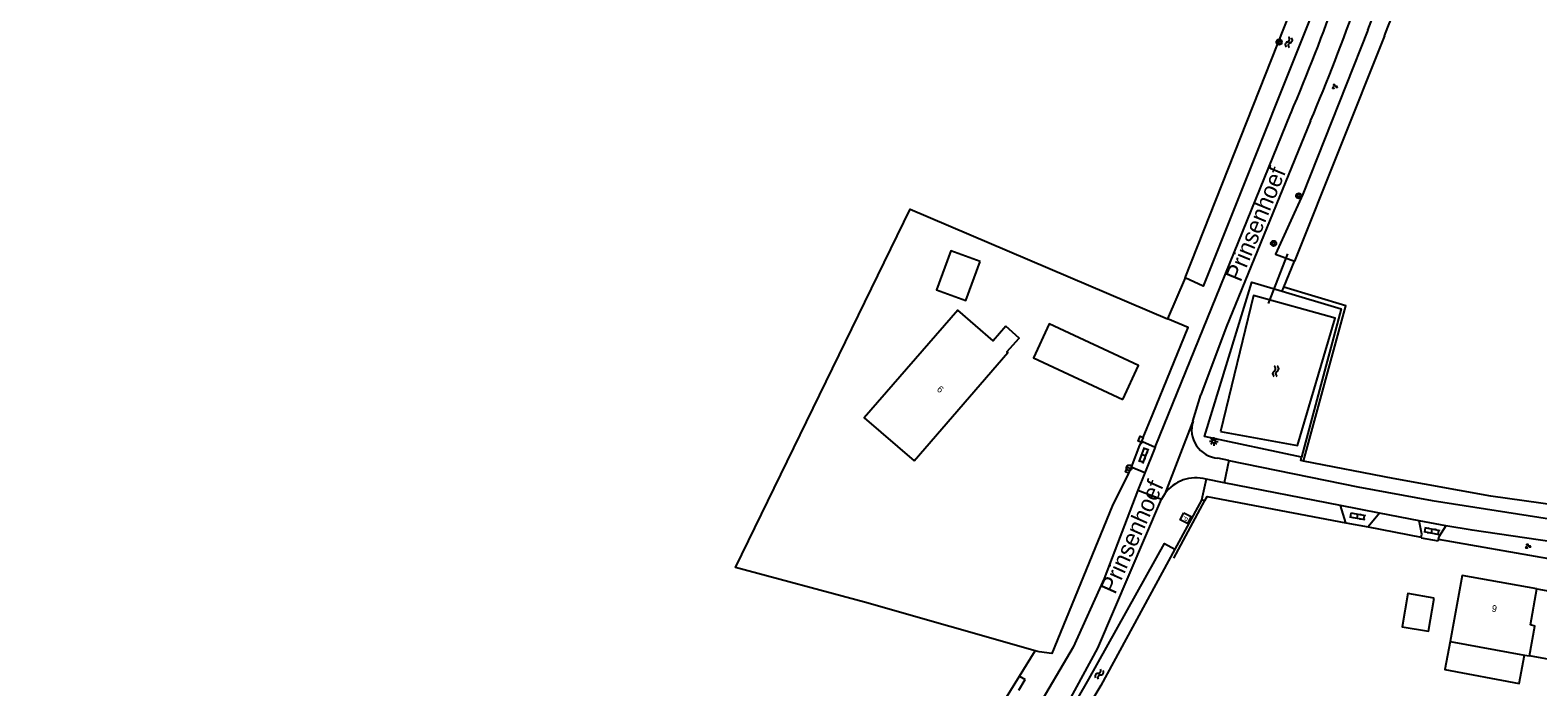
# Model space of a CAD drawing. Extents: x 124000 to 129000, y 395500 to 397503.
# Drawn here: x 125592.7 to 125816.2, y 397221.4 to 397318.7 of the extents above; entities that cross this region are included whole.
import ezdxf

# ---------------------------------------------------------------- set-up
doc = ezdxf.new("R2010")
doc.units = 0
for name, color, linetype in [('gg-afsc-draadraster', 7, 'Continuous'), ('gg-afsc-erfafscheiding', 7, 'Continuous'), ('gg-afsc-hekwerk', 7, 'Continuous'), ('gg-afsc-muur', 7, 'Continuous'), ('gg-anno-huisnummerreeks BGT', 7, 'Continuous'), ('gg-anno-openbare ruimte label', 7, 'Continuous'), ('gg-bbg-bijgebouw', 7, 'Continuous'), ('gg-bbg-gedigitaliseerde bebouwing', 7, 'Continuous'), ('gg-bbg-gedigitaliseerde bijgebouw', 7, 'Continuous'), ('gg-bbg-hoofdgebouw', 7, 'Continuous'), ('gg-bbg-luifel en loopbrug', 7, 'Continuous'), ('gg-bbg-tussenscheiding', 7, 'Continuous'), ('gg-knt-bronhoudergrens', 7, 'Continuous'), ('gg-knt-onverhard', 7, 'Continuous'), ('gg-knt-verharding', 7, 'Continuous'), ('gg-knt-verharding nz', 7, 'Continuous'), ('gg-kntw-bovenkant insteek waterloop', 7, 'Continuous'), ('gg-kwrk-duiker nz buis', 7, 'Continuous'), ('gt-grn-groengrens', 7, 'Continuous'), ('gt-grn-vlakafsluiter', 7, 'Continuous'), ('gt-grn-weggrens', 7, 'Continuous'), ('gt-symb-boom', 7, 'Continuous'), ('gt-symb-brandput', 7, 'Continuous'), ('gt-symb-groenvak', 7, 'Continuous'), ('gt-symb-hoogtemerk', 7, 'Continuous'), ('gt-symb-klinker verharding', 7, 'Continuous'), ('gt-symb-lichtmast', 7, 'Continuous'), ('gt-symb-watersymbool', 7, 'Continuous')]:
    doc.layers.add(name, color=color, linetype=linetype)

# ---------------------------------------------------------------- blocks, each defined once
blk = doc.blocks.new('gt0-BOOM')
at = {"layer": 'gt-symb-boom'}
for radius in [0.4, 0.2]:
    blk.add_circle((0, 0), radius, dxfattribs=at)
blk = doc.blocks.new('gt0-WA')
at = {"layer": 'gt-symb-watersymbool'}
for centre, start, end in [((-0.32, 0.02), 28.0725, 151.9275), ((0.43, 0.42), 208.0725, 331.9275), ((-0.32, -0.43), 28.0725, 151.9275), ((0.43, -0.03), 208.0725, 331.9275)]:
    blk.add_arc(centre, 0.425, start, end, dxfattribs=at)
blk = doc.blocks.new('gt0-KL1')
at = {"layer": 'gt-symb-klinker verharding'}
for p, q in [((-1.15, 0.3), (1.15, 0.3)), ((-1, -0.3), (-1, 0.3)), ((-0.5, 0.3), (-0.5, 0.45)), ((0, -0.3), (0, 0.3)), ((0.5, 0.3), (0.5, 0.45)), ((1, -0.3), (1, 0.3)), ((-1.15, -0.3), (1.15, -0.3)), ((-0.5, -0.45), (-0.5, -0.3)), ((0.5, -0.45), (0.5, -0.3))]:
    blk.add_line(p, q, dxfattribs=at)
blk = doc.blocks.new('gt0-LMAST')
at = {"layer": 'gt-symb-lichtmast'}
for p, q in [((-0.18, 0.17), (-0.45, 0.44)), ((-0.01, 0.25), (-0.01, 0.62)), ((0.17, 0.17), (0.44, 0.44)), ((-0.26, 0), (-0.63, 0)), ((-0.18, -0.18), (-0.45, -0.45)), ((-0.01, -0.25), (-0.01, -0.63)), ((0.44, -0.45), (0.17, -0.18)), ((0.24, 0), (0.62, 0))]:
    blk.add_line(p, q, dxfattribs=at)
blk.add_circle((-0.01, 0), 0.25, dxfattribs=at)
blk = doc.blocks.new('gt0-GRVAK')
at = {"layer": 'gt-symb-groenvak'}
for p, q in [((-0.11, 0.19), (-0.23, 0.24)), ((-0.18, 0.15), (0.09, 0.15)), ((-0.09, 0.21), (-0.16, 0.32)), ((-0.05, 0.21), (-0.05, 0.39)), ((0, 0.21), (0.06, 0.32)), ((0.01, 0.19), (0.13, 0.24)), ((0.26, -0.05), (0.2, 0.06)), ((0.3, -0.05), (0.3, 0.13)), ((0.35, -0.05), (0.41, 0.06)), ((-0.25, -0.23), (-0.36, -0.18)), ((-0.32, -0.26), (-0.05, -0.26)), ((-0.23, -0.21), (-0.29, -0.09)), ((-0.18, -0.2), (-0.18, -0.02)), ((-0.14, -0.21), (-0.07, -0.09)), ((-0.12, -0.23), (0, -0.18)), ((0.24, -0.07), (0.12, -0.02)), ((0.17, -0.11), (0.44, -0.11)), ((0.37, -0.07), (0.49, -0.02))]:
    blk.add_line(p, q, dxfattribs=at)
blk = doc.blocks.new('gt0-BPUT')
at = {"layer": 'gt-symb-brandput'}
blk.add_lwpolyline([(-0.6, -0.6), (-0.6, 0.6), (0.6, 0.6), (0.6, -0.6)], close=True, dxfattribs=at)
blk.add_text('P', height=0.7, dxfattribs=at).set_placement((-0.23, -0.35))
blk = doc.blocks.new('gt0-HMERK')
at = {"layer": 'gt-symb-hoogtemerk'}
blk.add_circle((0, 0), 0.4, dxfattribs=at)
blk.add_text('N.A.P', height=0.2, dxfattribs=at).set_placement((-0.35, -0.1))

msp = doc.modelspace()

# ---------------------------------------------------------------- linework, layer by layer
at = {"layer": 'gg-afsc-draadraster'}
for p, q in [((125742.29, 397226.56), (125741.72, 397226.72)), ((125739.37, 397222.94), (125740.23, 397222.45))]:
    msp.add_line(p, q, dxfattribs=at)
for points in [[(125741.72, 397226.72), (125716.39, 397233.93), (125697.28, 397239.08), (125723.17, 397292.15), (125761.34, 397275.92)], [(125781.5, 397254.82), (125787.78, 397277.85), (125778.58, 397280.61)], [(125642.65, 397110.93), (125650.08, 397115.76), (125657.43, 397120.69), (125663.34, 397125.22), (125669.13, 397130.47), (125677.55, 397139.59), (125698.48, 397164.07), (125708.62, 397176.8), (125716.67, 397187.69), (125724.43, 397198.85), (125739.37, 397222.94)]]:
    msp.add_lwpolyline(points, dxfattribs=at)
at = {"layer": 'gg-afsc-erfafscheiding'}
for p, q in [((125762.26, 397240.47), (125766.86, 397248.97)), ((125791.07, 397245.07), (125798.95, 397243.56)), ((125801.47, 397243.24), (125817.83, 397240.38))]:
    msp.add_line(p, q, dxfattribs=at)
msp.add_lwpolyline([(125766.86, 397248.97), (125767.19, 397249.57), (125787.74, 397245.69)], dxfattribs=at)
at = {"layer": 'gg-afsc-hekwerk'}
for points in [[(125781.21, 397255.43), (125766.81, 397258.46), (125773.81, 397281.37), (125778.34, 397280)], [(125778.34, 397280), (125787.07, 397277.38), (125781.21, 397255.43)], [(125781.5, 397254.82), (125781.1, 397254.9), (125781.21, 397255.43)], [(125860.69, 397244.76), (125860, 397244.82), (125859.93, 397243.49), (125842.01, 397245.47), (125824.09, 397247.55), (125809.27, 397249.63), (125794.76, 397252.24), (125781.5, 397254.82)]]:
    msp.add_lwpolyline(points, dxfattribs=at)
at = {"layer": 'gg-afsc-muur'}
for p, q in [((125757.73, 397258.34), (125757.44, 397257.63)), ((125755.86, 397253.76), (125755.56, 397253.03))]:
    msp.add_line(p, q, dxfattribs=at)
for points in [[(125757.44, 397257.63), (125756.99, 397257.81), (125757.29, 397258.53), (125757.73, 397258.34)], [(125755.56, 397253.03), (125755.1, 397253.23), (125755.4, 397253.95), (125755.86, 397253.76)]]:
    msp.add_lwpolyline(points, dxfattribs=at)
at = {"layer": 'gg-bbg-bijgebouw'}
for points in [[(125754.69, 397263.97), (125757.04, 397269.02), (125743.8, 397275.17), (125741.45, 397270.12), (125754.69, 397263.97)], [(125800.88, 397234.51), (125796.95, 397235.2), (125796.09, 397230.29), (125800.02, 397229.61), (125800.88, 397234.51)]]:
    msp.add_lwpolyline(points, dxfattribs=at)
at = {"layer": 'gg-bbg-gedigitaliseerde bebouwing'}
msp.add_lwpolyline([(125737.37, 397274.84), (125735.46, 397272.65), (125730.23, 397277.21), (125716.37, 397261.27), (125723.77, 397254.85)], dxfattribs=at)
at = {"layer": 'gg-bbg-gedigitaliseerde bijgebouw'}
msp.add_lwpolyline([(125733.55, 397284.42), (125729.22, 397286.01), (125727.09, 397280.23), (125731.43, 397278.64), (125733.55, 397284.42)], dxfattribs=at)
at = {"layer": 'gg-bbg-hoofdgebouw'}
for p, q in [((125803.23, 397228.08), (125814.25, 397226.09)), ((125814.25, 397226.09), (125815.01, 397225.95))]:
    msp.add_line(p, q, dxfattribs=at)
for points in [[(125723.77, 397254.85), (125737.67, 397270.95), (125737.51, 397271.02), (125739.35, 397273.05), (125737.37, 397274.84)], [(125816.06, 397235.9), (125805, 397237.9), (125803.23, 397228.08)], [(125816.06, 397235.9), (125827.85, 397233.78), (125826.08, 397223.96), (125815.01, 397225.95)]]:
    msp.add_lwpolyline(points, dxfattribs=at)
at = {"layer": 'gg-bbg-luifel en loopbrug'}
msp.add_lwpolyline([(125803.23, 397228.08), (125802.45, 397223.95), (125813.45, 397221.88), (125814.25, 397226.09)], dxfattribs=at)
at = {"layer": 'gg-bbg-tussenscheiding'}
msp.add_lwpolyline([(125815.01, 397225.95), (125815.76, 397230.38), (125815.13, 397230.59), (125816.06, 397235.9)], dxfattribs=at)
at = {"layer": 'gg-knt-bronhoudergrens'}
msp.add_line((125739.37, 397222.94), (125741.72, 397226.72), dxfattribs=at)
at = {"layer": 'gg-knt-onverhard'}
for points in [[(125756.93, 397250.55), (125751.92, 397237.41), (125747.34, 397227.24), (125741.75, 397217.78), (125735.38, 397208.19), (125729.64, 397199.42), (125720.97, 397187.07), (125714.45, 397178.02), (125707.31, 397168.67), (125700.08, 397159.6), (125693.27, 397151.32), (125685.78, 397142.8), (125678.08, 397134.37), (125669.79, 397126.12), (125660.96, 397118.64), (125651.56, 397112.01), (125641.81, 397105.88), (125631.9, 397099.39), (125622.1, 397093.12), (125612.4, 397086.72), (125602.25, 397080.32), (125592.69, 397074.68)], [(125594.39, 397071.5), (125605.9, 397078.13), (125617.48, 397085.31), (125629.25, 397092.48), (125640.98, 397100.11), (125652.95, 397108.25), (125661.79, 397114.35), (125670.36, 397121.2), (125679.79, 397130.22), (125688.65, 397139.93), (125697.18, 397149.89), (125705.54, 397160.37), (125714.15, 397171.43), (125722.32, 397182.61), (125729.65, 397193.12), (125737.34, 397204.28), (125744.49, 397215.1), (125750.97, 397227.13), (125760.44, 397249.2)]]:
    msp.add_lwpolyline(points, dxfattribs=at)
at = {"layer": 'gg-knt-verharding'}
for p, q in [((125759.5, 397256.88), (125779.6, 397306.38)), ((125765.1, 397260.77), (125766.24, 397264.67)), ((125759.5, 397256.88), (125757.96, 397253.08)), ((125770.4, 397254.94), (125768.8, 397255.27)), ((125757.96, 397253.08), (125755.93, 397253.94)), ((125757.96, 397253.08), (125756.93, 397250.55)), ((125756.93, 397250.55), (125760.44, 397249.2)), ((125769.74, 397251.61), (125767.03, 397252.14)), ((125786.98, 397248.24), (125769.74, 397251.61)), ((125760.92, 397250), (125760.44, 397249.2)), ((125792.75, 397247.11), (125786.98, 397248.24)), ((125787.74, 397245.69), (125786.98, 397248.24)), ((125792.75, 397247.11), (125791.07, 397245.07)), ((125798.64, 397245.96), (125792.75, 397247.11)), ((125802.6, 397245.24), (125798.64, 397245.96)), ((125798.93, 397243.44), (125798.95, 397243.56)), ((125801.47, 397243.24), (125801.43, 397243.01))]:
    msp.add_line(p, q, dxfattribs=at)
for points in [[(125782.53, 397305.26), (125770.03, 397274.69), (125766.24, 397264.67)], [(125757.17, 397257.2), (125757.62, 397257.73), (125759.5, 397256.88)], [(125770.4, 397254.94), (125789.54, 397251), (125800.58, 397249.01), (125821.12, 397245.8), (125842.23, 397243.55), (125858.93, 397242.05), (125886.98, 397239.73), (125895.9, 397239.33)], [(125798.95, 397243.56), (125799.03, 397244.01), (125798.64, 397245.96)], [(125802.6, 397245.24), (125801.54, 397243.6), (125801.47, 397243.24)], [(125818.28, 397242.85), (125806.48, 397244.61), (125802.6, 397245.24)]]:
    msp.add_lwpolyline(points, dxfattribs=at)
for centre, radius, start, end in [((125495.48, 397427.25), 308.77, 336.9529, 344.0467), ((125497.35, 397426.68), 309.95, 336.9367, 344.0641), ((125769.12, 397259.47), 4.22, 162.1014, 265.6434), ((125765.49, 397246.73), 5.62, 74.0858, 144.4358)]:
    msp.add_arc(centre, radius, start, end, dxfattribs=at)
at = {"layer": 'gg-knt-verharding nz'}
msp.add_line((125770.4, 397254.94), (125769.74, 397251.61), dxfattribs=at)
at = {"layer": 'gg-kntw-bovenkant insteek waterloop'}
msp.add_line((125793.48, 397317.87), (125780.13, 397284.47), dxfattribs=at)
for points in [[(125787.48, 397342.4), (125789.8, 397341.66), (125786.9, 397331.61), (125766.62, 397280.77), (125763.93, 397282)], [(125763.93, 397282), (125784.1, 397332.97), (125786.34, 397340.47)], [(125791.02, 397318.7), (125781.38, 397294.39), (125777.34, 397285.49), (125780.13, 397284.47)], [(125769.18, 397259.22), (125780.62, 397257.14), (125786.2, 397276), (125774.08, 397279.38), (125769.18, 397259.22)], [(125737.33, 397198.19), (125736.58, 397198.69), (125736.62, 397199.8), (125749.64, 397222.5), (125760.87, 397242.64), (125762.4, 397241.8)], [(125762.4, 397241.8), (125751.42, 397221.6), (125738.26, 397199.47)]]:
    msp.add_lwpolyline(points, dxfattribs=at)
for centre, radius, start, end in [((125598.49, 397393.73), 206.63, 338.7096, 350.9678), ((125633.52, 397382.7), 172.6, 337.9377, 352.7779)]:
    msp.add_arc(centre, radius, start, end, dxfattribs=at)
at = {"layer": 'gg-kwrk-duiker nz buis'}
msp.add_line((125776.28, 397278.18), (125779.14, 397285.55), dxfattribs=at)
at = {"layer": 'gt-grn-groengrens'}
for p, q in [((125778.58, 397280.61), (125780.13, 397284.47)), ((125763.93, 397282), (125761.34, 397275.92)), ((125778.34, 397280), (125778.58, 397280.61)), ((125757.44, 397257.63), (125757.17, 397257.2)), ((125755.56, 397253.03), (125753.12, 397248.17)), ((125755.93, 397253.94), (125755.86, 397253.76)), ((125767.03, 397252.14), (125766.37, 397249.06)), ((125766.37, 397249.06), (125762.4, 397241.8)), ((125766.86, 397248.97), (125766.37, 397249.06))]:
    msp.add_line(p, q, dxfattribs=at)
for points in [[(125757.73, 397258.34), (125759.17, 397261.77), (125764.4, 397274.61), (125761.34, 397275.92)], [(125753.12, 397248.17), (125744.18, 397226.33), (125742.29, 397226.56)]]:
    msp.add_lwpolyline(points, dxfattribs=at)
at = {"layer": 'gt-grn-vlakafsluiter'}
msp.add_line((125739.27, 397220.88), (125740.23, 397222.45), dxfattribs=at)
at = {"layer": 'gt-grn-weggrens'}
for p, q in [((125765.1, 397260.77), (125760.92, 397250)), ((125757.17, 397257.2), (125755.93, 397253.94)), ((125787.74, 397245.69), (125791.07, 397245.07)), ((125798.93, 397243.44), (125801.43, 397243.01))]:
    msp.add_line(p, q, dxfattribs=at)

# ---------------------------------------------------------------- block references
at = {"layer": 'gt-symb-boom'}
for p in [(125777.87, 397316.93), (125780.78, 397294.15), (125777.05, 397287.1)]:
    msp.add_blockref('gt0-BOOM', p, dxfattribs=at)
at = {"layer": 'gt-symb-brandput', "rotation": -116.7455097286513}
msp.add_blockref('gt0-BPUT', (125764.01, 397246.38), dxfattribs=at)
at = {"layer": 'gt-symb-groenvak'}
for p in [(125786.09, 397310.35), (125814.74, 397242.23)]:
    msp.add_blockref('gt0-GRVAK', p, dxfattribs=at)
at = {"layer": 'gt-symb-hoogtemerk'}
msp.add_blockref('gt0-HMERK', (125755.63, 397253.85), dxfattribs=at)
at = {"layer": 'gt-symb-klinker verharding'}
for p, rotation in [((125757.8, 397255.68), 68.9542591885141), ((125789.51, 397246.66), -9.905079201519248), ((125800.52, 397244.47), -10.309970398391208)]:
    msp.add_blockref('gt0-KL1', p, dxfattribs=dict(at, rotation=rotation))
at = {"layer": 'gt-symb-lichtmast'}
msp.add_blockref('gt0-LMAST', (125768.19, 397257.75), dxfattribs=at)
at = {"layer": 'gt-symb-watersymbool'}
for p, rotation in [((125779.33, 397316.95), -103.06333733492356), ((125777.36, 397268.21), -90.00000000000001), ((125751.18, 397223.21), 59.871399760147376)]:
    msp.add_blockref('gt0-WA', p, dxfattribs=dict(at, rotation=rotation))

# ---------------------------------------------------------------- texts
at = {"layer": 'gg-anno-huisnummerreeks BGT'}
for s, rotation, p in [('6', 319.2, (125727.03, 397265.34)), ('9', 349.7, (125809.33, 397232.55))]:
    msp.add_text(s, height=1, rotation=rotation, dxfattribs=at).set_placement(p)
at = {"layer": 'gg-anno-openbare ruimte label'}
for rotation, p in [(67.7, (125772.16, 397281.26)), (66, (125753.54, 397234.97))]:
    msp.add_text('Prinsenhoef', height=2.5, rotation=rotation, dxfattribs=at).set_placement(p)

doc.saveas('drawing.dxf')
